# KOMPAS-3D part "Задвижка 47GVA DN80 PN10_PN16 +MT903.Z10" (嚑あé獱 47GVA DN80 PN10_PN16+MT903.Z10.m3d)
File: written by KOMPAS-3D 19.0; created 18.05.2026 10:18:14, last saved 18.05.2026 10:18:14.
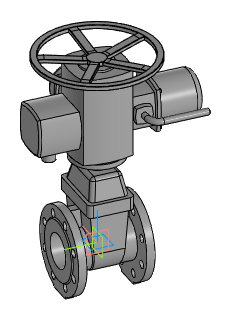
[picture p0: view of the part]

Document properties: Автор: Энергия; Полное имя файла: ..\Задвижка 47GVA DN50_DN1000+MT903.Z\Задвижка 47GVA DN80 PN10_PN16+MT903.Z10.a3d

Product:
- Part/product: Задвижка 47GVA DN80 PN10_PN16 +MT903.Z10
    Масса: 76.272
  - Body: Электропривод MT903.Z05-15
      Масса: 49.8062
  - Body: Задвижка 47GVA DN80 PN10_PN16 без исполнит. мех.
      Масса: 26.4658

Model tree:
1. Операция без истории:1
2. Операция без истории:2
